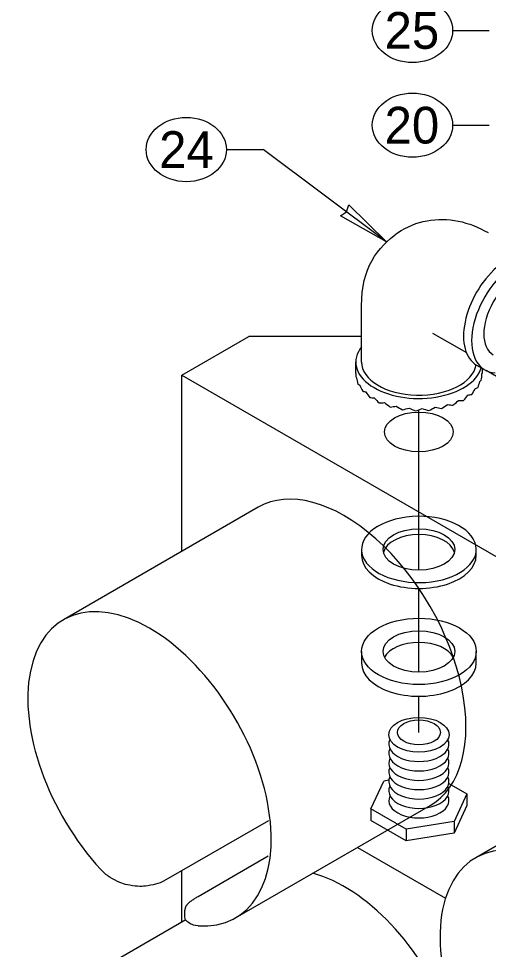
# Model space of a CAD drawing. Extents: x 99862 to 104211, y 98939 to 105076.
# Drawn here: x 101813.1 to 102017.8, y 101211.1 to 101616.6 of the extents above; entities that cross this region are included whole.
import ezdxf

# ---------------------------------------------------------------- set-up
doc = ezdxf.new("R2010")
doc.units = 0
for name, color, linetype in [('Level 11', 7, 'Continuous'), ('Level 15', 7, 'Continuous'), ('Level 2', 7, 'Continuous'), ('Level 20', 7, 'Continuous'), ('Level 26', 7, 'Continuous'), ('Level 3', 7, 'Continuous'), ('Level 4', 7, 'Continuous'), ('Level 5', 7, 'Continuous'), ('Level 7', 7, 'Continuous')]:
    doc.layers.add(name, color=color, linetype=linetype)

msp = doc.modelspace()

# ---------------------------------------------------------------- linework, layer by layer
at = {"layer": 'Level 11'}
for p, q in [((101962.57, 101385.35), (101962.57, 101382.8)), ((102012.57, 101382.8), (102012.57, 101385.35)), ((101962.57, 101340.93), (101962.57, 101335.82)), ((102012.57, 101335.82), (102012.57, 101340.93))]:
    msp.add_line(p, q, dxfattribs=at)
for centre in [(101987.57, 101385.35), (101987.57, 101340.93)]:
    msp.add_ellipse(centre, major_axis=(15.62, 0), ratio=0.57735, dxfattribs=at)
for centre, major_axis, start_param, end_param in [((101987.57, 101382.8), (-15.62, 0), 3.28349, 6.141288), ((101987.57, 101382.8), (-25, 0), 0, 3.141593), ((101987.57, 101335.82), (-15.62, 0), 3.428349, 5.996429), ((101987.57, 101335.82), (-25, 0), 6.283185, 9.424778)]:
    msp.add_ellipse(centre, major_axis=major_axis, ratio=0.57735, start_param=start_param, end_param=end_param, dxfattribs=at)
at = {"layer": 'Level 15'}
for p, q in [((102002.26, 101611.44), (102018.26, 101611.44)), ((102002.26, 101570.18), (102018.26, 101570.18)), ((101903.72, 101559.55), (101919.72, 101559.55)), ((101973.48, 101519.43), (101919.72, 101559.55)), ((101987.57, 101376.33), (101987.57, 101446.19)), ((101987.57, 101331.9), (101987.57, 101368.37)), ((101987.57, 101305.65), (101987.57, 101321.39))]:
    msp.add_line(p, q, dxfattribs=at)
msp.add_lwpolyline([(101973.48, 101519.43), (101953.4, 101530.69), (101956.03, 101532.45), (101956.97, 101535.48)], close=True, dxfattribs=at)
at = {"layer": 'Level 2'}
for p, q in [((102008.49, 101278.88), (102002.88, 101266.8)), ((101981.97, 101263.57), (101966.66, 101272.4)), ((102002.88, 101266.8), (101981.97, 101263.57)), ((102002.88, 101266.8), (102002.88, 101261.7)), ((101981.97, 101263.57), (101981.97, 101258.46))]:
    msp.add_line(p, q, dxfattribs=at)
msp.add_ellipse((101987.57, 101305.65), major_axis=(-9.38, 0), ratio=0.57735, dxfattribs=at)
for centre, start_param, end_param in [((101987.57, 101300.54), 2.86885, 6.555928), ((101987.57, 101296.46), 2.86885, 6.555928), ((101987.57, 101292.3), 2.86338, 6.561398), ((101987.57, 101288.3), 2.874311, 6.550467), ((101987.57, 101284.21), 2.86885, 6.555928), ((101987.57, 101280.13), 2.86885, 6.555928)]:
    msp.add_ellipse(centre, major_axis=(13.12, 0), ratio=0.57735, start_param=start_param, end_param=end_param, dxfattribs=at)
at = {"layer": 'Level 20'}
for p, q in [((101962.57, 101467), (101962.57, 101491.5)), ((101960.07, 101462.07), (101960.07, 101467)), ((102015.07, 101464.28), (102015.07, 101462.07))]:
    msp.add_line(p, q, dxfattribs=at)
for centre in [(101984.76, 101611.44), (101984.76, 101570.18), (101886.22, 101559.55)]:
    msp.add_ellipse(centre, major_axis=(-17.5, 0), ratio=0.8, dxfattribs=at)
for centre, major_axis, ratio, start_param, end_param in [((102030, 101487.42), (13.75, 23.82), 0.57735, 5.990419, 9.717544), ((102030, 101487.42), (-10, -17.32), 0.57735, 3.143881, 6.280897), ((101987.57, 101462.61), (-27.03, -5.37), 0.947565, 6.097095, 6.149455), ((101987.57, 101462.61), (-27.5, -1.68), 0.206802, 0.039705, 0.144424), ((101987.57, 101462.61), (-27.03, -5.37), 0.947565, 2.798769, 2.903143), ((101987.57, 101462.61), (25.29, -11.7), 0.922162, 3.702024, 3.806744), ((101987.57, 101462.61), (-27.49, -3.89), 0.223561, 0.230203, 0.334923), ((101987.57, 101462.61), (24.12, -15.48), 0.853385, 4.009326, 4.114045), ((101987.57, 101462.61), (-24.52, -14.02), 0.887795, 2.305204, 2.41027), ((101987.57, 101462.61), (27.49, -2.78), 0.21596, 6.043201, 6.148266), ((101987.57, 101462.61), (-27.46, -6), 0.252109, 0.416228, 0.520948), ((101987.57, 101462.61), (24.3, -16.43), 0.783391, 4.204501, 4.309221), ((101987.57, 101462.61), (-24.54, -16.55), 0.749264, 1.888318, 1.993037), ((101987.57, 101462.61), (27.43, -7.01), 0.270119, 5.671382, 5.776101), ((101987.57, 101462.61), (-24.14, -16.11), 0.818147, 2.06586, 2.17058), ((101987.57, 101462.61), (27.48, -4.96), 0.236491, 5.854579, 5.958953), ((101987.57, 101462.61), (-27.4, -7.98), 0.290225, 0.596374, 0.701094), ((101987.57, 101462.61), (24.82, -16.54), 0.715795, 4.372134, 4.476854), ((101987.57, 101462.61), (-27.3, -9.8), 0.335596, 0.770216, 0.874936), ((101987.57, 101462.61), (25.39, -16.22), 0.650745, 4.530376, 4.635096), ((101987.57, 101462.61), (-25.67, -15.94), 0.6191, 1.570348, 1.675068), ((101987.57, 101462.61), (27.23, -10.65), 0.360362, 5.323611, 5.42833), ((101987.57, 101462.61), (-25.11, -16.43), 0.682966, 1.726553, 1.831273), ((101987.57, 101462.61), (27.36, -8.91), 0.312139, 5.494389, 5.599109), ((101987.57, 101462.61), (-27.14, -11.45), 0.386234, 0.938087, 1.042807), ((101987.57, 101462.61), (25.93, -15.58), 0.588004, 4.685558, 4.790278), ((101987.57, 101462.61), (-26.91, -12.9), 0.440657, 1.100807, 1.205527), ((101987.57, 101462.61), (26.39, -14.68), 0.527399, 4.840753, 4.945473), ((101987.57, 101462.61), (-26.58, -14.14), 0.497899, 1.259485, 1.364205), ((101987.57, 101462.61), (26.76, -13.55), 0.468967, 4.997892, 5.102611), ((101987.57, 101462.61), (-26.17, -15.16), 0.557438, 1.415448, 1.520168), ((101987.57, 101462.61), (27.03, -12.2), 0.413044, 5.158439, 5.263158)]:
    msp.add_ellipse(centre, major_axis=major_axis, ratio=ratio, start_param=start_param, end_param=end_param, dxfattribs=at)
msp.add_open_spline([(101962.57, 101491.5), (101962.58, 101499.73), (101965.92, 101512.29), (101978.25, 101524.4), (101990.95, 101529.45), (102004.87, 101529.2), (102013.62, 101525.74), (102017.75, 101523.36)], degree=3, dxfattribs=at)
at = {"layer": 'Level 26'}
for p, q in [((101884.33, 101461.28), (101913.39, 101478.05)), ((101962.57, 101478.05), (101913.39, 101478.05)), ((101884.33, 101384.58), (101884.33, 101461.28)), ((101884.33, 101461.28), (102025.75, 101379.63)), ((102021.4, 101460.66), (102016.88, 101463.27)), ((101917.54, 101403.75), (101832.69, 101354.76)), ((102059.66, 101278.37), (102012.33, 101251.05)), ((101907.69, 101224.86), (101992.54, 101273.85)), ((101921.96, 101267.18), (101877.26, 101241.37)), ((101960.84, 101255.55), (101999.16, 101233.42)), ((101960.84, 101255.55), (101999.16, 101233.42)), ((101891.4, 101234.23), (101921.86, 101251.82)), ((101884.33, 101223.02), (101884.33, 101245.45)), ((101885.54, 101225.88), (101885.54, 101226.93)), ((101886.04, 101224.01), (101832.69, 101193.21))]:
    msp.add_line(p, q, dxfattribs=at)
msp.add_ellipse((101987.57, 101436.54), major_axis=(15, 0), ratio=0.57735, dxfattribs=at)
for centre, start_param, end_param in [((101955.04, 101338.8), 0, 3.141593), ((101870.19, 101289.81), 5.909304, 11.369456), ((102049.83, 101186.09), 5.909304, 11.369456), ((101955.04, 101177.25), 0, 2.616954)]:
    msp.add_ellipse(centre, major_axis=(37.5, -64.95), ratio=0.57735, start_param=start_param, end_param=end_param, dxfattribs=at)
for points, degree in [([(101877.26, 101241.37), (101875.35, 101240.27), (101873.08, 101239.46), (101868.12, 101238.57), (101865.44, 101238.5), (101860.17, 101239.23), (101857.55, 101240.04), (101852.84, 101242.44), (101850.73, 101244.04), (101848.97, 101245.94)], 3), ([(101885.54, 101226.91), (101885.54, 101229.24), (101887.65, 101232.07), (101891.4, 101234.23)], 2), ([(101891.4, 101221.44), (101889.65, 101221.57), (101888.21, 101222.02), (101886.16, 101223.51), (101885.59, 101224.54), (101885.54, 101225.76), (101885.54, 101225.8), (101885.54, 101225.84)], 3)]:
    msp.add_open_spline(points, degree=degree, dxfattribs=at)
at = {"layer": 'Level 3'}
for p, q in [((101966.66, 101272.4), (101972.27, 101284.48)), ((101974.49, 101284.82), (101972.27, 101284.48)), ((102000.63, 101283.41), (102008.49, 101278.88)), ((102008.49, 101278.88), (102008.49, 101273.77)), ((101966.66, 101272.4), (101966.66, 101267.3)), ((102008.49, 101273.77), (102002.88, 101261.7)), ((101981.97, 101258.46), (101966.66, 101267.3)), ((102002.88, 101261.7), (101981.97, 101258.46))]:
    msp.add_line(p, q, dxfattribs=at)
msp.add_ellipse((101987.57, 101304.63), major_axis=(13.12, 0), ratio=0.57735, dxfattribs=at)
msp.add_ellipse((101987.57, 101275.96), major_axis=(13.12, 0), ratio=0.57735, start_param=2.862617, end_param=6.56216, dxfattribs=at)
at = {"layer": 'Level 4'}
msp.add_ellipse((101987.57, 101340.93), major_axis=(25, 0), ratio=0.57735, dxfattribs=at)
at = {"layer": 'Level 5'}
msp.add_ellipse((101987.57, 101385.35), major_axis=(25, 0), ratio=0.57735, start_param=1.690716, end_param=7.973165, dxfattribs=at)
at = {"layer": 'Level 7'}
for p, q in [((101993.51, 101479.62), (102008.24, 101471.11)), ((102012.72, 101465.64), (102016.25, 101463.6))]:
    msp.add_line(p, q, dxfattribs=at)
for centre, major_axis, ratio, start_param, end_param in [((102026.47, 101489.46), (13.75, 23.82), 0.57735, 0, 3.141593), ((101987.57, 101467), (27.5, 0), 0.57735, 2.711893, 6.123637), ((101987.57, 101467), (25, 0), 0.57735, 3.141593, 6.198272), ((101987.57, 101462.61), (27.5, -0.56), 0.203365, 6.234982, 6.287342)]:
    msp.add_ellipse(centre, major_axis=major_axis, ratio=ratio, start_param=start_param, end_param=end_param, dxfattribs=at)

# ---------------------------------------------------------------- texts
at = {"layer": 'Level 20'}
for s, p in [('25', (101972.62, 101603.45)), ('20', (101972.62, 101562.18)), ('24', (101874.38, 101551.55))]:
    msp.add_text(s, height=16, dxfattribs=at).set_placement(p)

doc.saveas('drawing.dxf')
